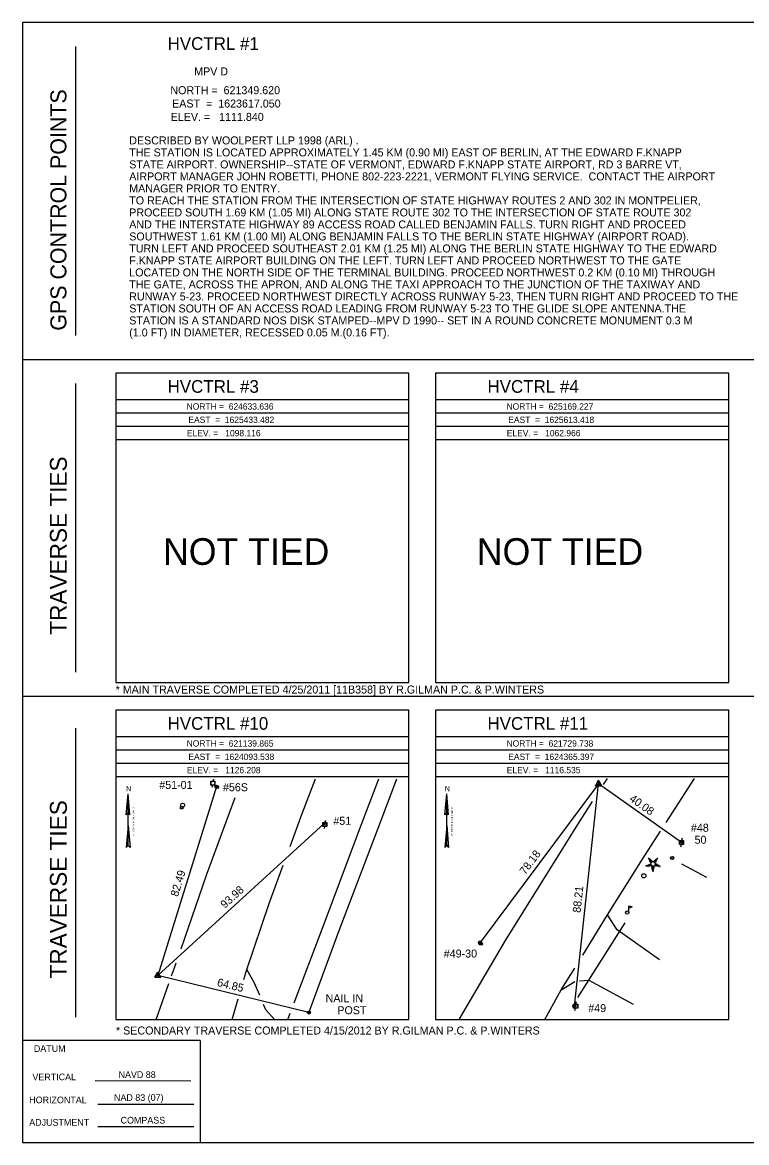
# Model space of a CAD drawing. Extents: x 1624370 to 1625010, y 624015 to 624435.
# Drawn here: x 1624369.8 to 1624641.5, y 624015.5 to 624435.5 of the extents above; entities that cross this region are included whole.
import ezdxf

# ---------------------------------------------------------------- set-up
doc = ezdxf.new("R2010")
doc.units = 0
for name, color, linetype in [('C_C', 7, 'Continuous'), ('CBP', 7, 'Continuous'), ('CPBM', 7, 'Continuous'), ('CPSM', 7, 'Continuous'), ('DCP', 7, 'Continuous'), ('Default', 7, 'Continuous'), ('LAHR', 7, 'Continuous'), ('LFNC', 7, 'Continuous'), ('LMB', 7, 'Continuous'), ('LTC', 7, 'Continuous'), ('MPIP', 7, 'Continuous'), ('NBL1', 7, 'Continuous'), ('NBL2', 7, 'Continuous'), ('NNA_P', 7, 'Continuous'), ('PET', 7, 'Continuous'), ('RDP', 7, 'Continuous'), ('U_C', 7, 'Continuous'), ('UP', 7, 'Continuous'), ('UPGW', 7, 'Continuous'), ('USMH', 7, 'Continuous')]:
    doc.layers.add(name, color=color, linetype=linetype)

msp = doc.modelspace()

# ---------------------------------------------------------------- linework, layer by layer
at = {"layer": 'CBP'}
for centre, radius in [((1624442.59, 624148.98), 0.562), ((1624442.59, 624148.98), 0.075), ((1624483.06, 624135.07), 0.562), ((1624483.06, 624135.07), 0.075), ((1624617.02, 624127.94), 0.594), ((1624617.02, 624127.94), 0.0792), ((1624541.46, 624090.47), 0.594), ((1624541.46, 624090.47), 0.0792), ((1624576.87, 624066.64), 0.594), ((1624576.87, 624066.64), 0.0792), ((1624477.25, 624064.25), 0.562), ((1624477.25, 624064.25), 0.075)]:
    msp.add_circle(centre, radius, dxfattribs=at)
at = {"layer": 'CPBM'}
for p, q in [((1624429.08, 624140.64), (1624429.08, 624141.54)), ((1624429.08, 624141.54), (1624429.98, 624141.54)), ((1624429.53, 624141.09), (1624429.53, 624141.09)), ((1624429.53, 624141.09), (1624429.53, 624141.09)), ((1624429.98, 624141.54), (1624429.98, 624140.64)), ((1624429.98, 624140.64), (1624429.08, 624140.64))]:
    msp.add_line(p, q, dxfattribs=at)
at = {"layer": 'CPSM'}
for p, q in [((1624584.76, 624149.26), (1624585.94, 624151.32)), ((1624584.76, 624149.26), (1624585.94, 624149.95)), ((1624587.13, 624149.26), (1624585.94, 624151.32)), ((1624585.94, 624149.95), (1624585.94, 624151.32)), ((1624585.94, 624149.95), (1624585.94, 624149.95)), ((1624585.94, 624149.95), (1624587.13, 624149.26)), ((1624584.76, 624149.26), (1624587.13, 624149.26)), ((1624419.42, 624077.44), (1624420.54, 624079.39)), ((1624419.42, 624077.44), (1624420.54, 624078.09)), ((1624421.67, 624077.44), (1624420.54, 624079.39)), ((1624420.54, 624078.09), (1624420.54, 624079.39)), ((1624420.54, 624078.09), (1624420.54, 624078.09)), ((1624420.54, 624078.09), (1624421.67, 624077.44)), ((1624419.42, 624077.44), (1624421.67, 624077.44))]:
    msp.add_line(p, q, dxfattribs=at)
at = {"layer": 'DCP'}
msp.add_lwpolyline([(1624578.15, 624069.82), (1624595.86, 624097.89)], dxfattribs=at)
at = {"layer": 'Default'}
for p, q in [((1624585.94, 624149.95), (1624541.46, 624090.47)), ((1624576.87, 624066.64), (1624585.94, 624149.95)), ((1624617.02, 624127.94), (1624585.94, 624149.95)), ((1624442.59, 624148.98), (1624420.54, 624078.09)), ((1624420.54, 624078.09), (1624483.06, 624135.07)), ((1624477.25, 624064.25), (1624420.54, 624078.09))]:
    msp.add_line(p, q, dxfattribs=at)
at = {"layer": 'LAHR'}
for points in [[(1624471.7, 624067.84), (1624482.36, 624095.81), (1624496.94, 624134.52), (1624503.46, 624151.8)], [(1624626.55, 624114.93), (1624617.14, 624119.83)], [(1624469.34, 624061.64), (1624470.23, 624063.98)]]:
    msp.add_lwpolyline(points, dxfattribs=at)
at = {"layer": 'LFNC'}
msp.add_lwpolyline([(1624477.2, 624064.07), (1624488.68, 624094.95), (1624504.26, 624136.01), (1624510.24, 624151.8)], dxfattribs=at)
at = {"layer": 'LMB'}
for p, q in [((1624597.3, 624104.22), (1624598.53, 624103.85)), ((1624597.31, 624101.75), (1624597.31, 624104.22)), ((1624597.31, 624103.36), (1624598.53, 624103.84)), ((1624596.68, 624101.74), (1624596.68, 624101.74))]:
    msp.add_line(p, q, dxfattribs=at)
msp.add_circle((1624596.68, 624101.74), 0.623, dxfattribs=at)
at = {"layer": 'LTC'}
for p, q in [((1624604.56, 624122.02), (1624604.9, 624122.26)), ((1624604.76, 624121.58), (1624605.26, 624121.94)), ((1624604.94, 624120.05), (1624605.26, 624119.08)), ((1624604.96, 624121.14), (1624605.63, 624121.62)), ((1624605.16, 624120.69), (1624605.99, 624121.3)), ((1624605.37, 624120.26), (1624606.33, 624120.96)), ((1624605.37, 624120.26), (1624605.74, 624119.13)), ((1624606.33, 624120.96), (1624607.28, 624120.27)), ((1624606.73, 624121.26), (1624607.5, 624120.7)), ((1624607.28, 624120.27), (1624606.91, 624119.13)), ((1624607.09, 624121.59), (1624607.73, 624121.12)), ((1624607.7, 624120.01), (1624607.38, 624119.02)), ((1624607.44, 624121.92), (1624607.96, 624121.54)), ((1624607.79, 624122.25), (1624608.19, 624121.96)), ((1624603.64, 624119.44), (1624603.79, 624118.99)), ((1624604.08, 624119.64), (1624604.28, 624119.02)), ((1624604.51, 624119.85), (1624604.77, 624119.05)), ((1624606.91, 624119.13), (1624605.74, 624119.13)), ((1624606.87, 624118.65), (1624605.79, 624118.65)), ((1624606.79, 624118.18), (1624605.86, 624118.18)), ((1624606.71, 624117.7), (1624605.92, 624117.7)), ((1624606.63, 624117.23), (1624605.99, 624117.23)), ((1624608.12, 624119.77), (1624607.85, 624118.93)), ((1624608.54, 624119.54), (1624608.32, 624118.84)), ((1624608.96, 624119.3), (1624608.79, 624118.75))]:
    msp.add_line(p, q, dxfattribs=at)
at = {"layer": 'MPIP'}
for radius in [0.594, 0.0792]:
    msp.add_circle((1624613.52, 624122.18), radius, dxfattribs=at)
at = {"layer": 'NBL1'}
msp.add_lwpolyline([(1624369.79, 624015.47), (1625009.79, 624015.47), (1625009.79, 624435.47), (1624369.79, 624435.47)], close=True, dxfattribs=at)
at = {"layer": 'NBL2'}
for p, q in [((1624389.79, 624318.14), (1624389.79, 624426.47)), ((1624369.79, 624309.14), (1625009.79, 624309.14)), ((1624389.79, 624191.81), (1624389.79, 624300.14)), ((1624514.79, 624293.97), (1624404.79, 624293.97)), ((1624634.79, 624293.97), (1624524.79, 624293.97)), ((1624514.79, 624288.97), (1624404.79, 624288.97)), ((1624634.79, 624288.97), (1624524.79, 624288.97)), ((1624514.79, 624283.97), (1624404.79, 624283.97)), ((1624634.79, 624283.97), (1624524.79, 624283.97)), ((1624514.79, 624278.97), (1624404.79, 624278.97)), ((1624634.79, 624278.97), (1624524.79, 624278.97)), ((1624369.79, 624182.81), (1625009.79, 624182.81)), ((1624389.79, 624062.47), (1624389.79, 624170.81)), ((1624514.79, 624167.64), (1624404.79, 624167.64)), ((1624634.79, 624167.64), (1624524.79, 624167.64)), ((1624514.79, 624162.64), (1624404.79, 624162.64)), ((1624634.79, 624162.64), (1624524.79, 624162.64)), ((1624514.79, 624157.64), (1624404.79, 624157.64)), ((1624634.79, 624157.64), (1624524.79, 624157.64)), ((1624514.79, 624152.64), (1624404.79, 624152.64)), ((1624634.79, 624152.64), (1624524.79, 624152.64)), ((1624436.45, 624053.73), (1624369.79, 624053.73)), ((1624436.45, 624053.73), (1624436.45, 624015.47)), ((1624436.45, 624053.73), (1624436.45, 624015.47)), ((1624397.03, 624038.7), (1624433.03, 624038.67)), ((1624398.14, 624029.93), (1624434.14, 624029.93)), ((1624398.14, 624021.49), (1624434.14, 624021.46))]:
    msp.add_line(p, q, dxfattribs=at)
for points in [[(1624404.79, 624187.97), (1624514.79, 624187.97), (1624514.79, 624303.97), (1624404.79, 624303.97)], [(1624524.79, 624187.97), (1624634.79, 624187.97), (1624634.79, 624303.97), (1624524.79, 624303.97)], [(1624404.79, 624061.64), (1624514.79, 624061.64), (1624514.79, 624177.64), (1624404.79, 624177.64)], [(1624524.79, 624061.64), (1624634.79, 624061.64), (1624634.79, 624177.64), (1624524.79, 624177.64)]]:
    msp.add_lwpolyline(points, close=True, dxfattribs=at)
at = {"layer": 'NNA_P'}
for p, q in [((1624408.76, 624138.4), (1624409.45, 624146.19)), ((1624409.46, 624126.81), (1624409.45, 624146.19)), ((1624410.15, 624138.4), (1624409.45, 624146.19)), ((1624528.28, 624138.4), (1624528.97, 624146.19)), ((1624528.97, 624126.81), (1624528.97, 624146.19)), ((1624529.66, 624138.4), (1624528.97, 624146.19)), ((1624408.76, 624138.4), (1624409.45, 624139.16)), ((1624410.15, 624138.4), (1624409.46, 624139.16)), ((1624528.28, 624138.4), (1624528.97, 624139.16)), ((1624529.67, 624138.4), (1624528.97, 624139.16)), ((1624409.46, 624134.34), (1624408.74, 624126.17)), ((1624409.45, 624134.34), (1624410.18, 624126.17)), ((1624528.97, 624134.34), (1624528.25, 624126.17)), ((1624528.97, 624134.34), (1624529.69, 624126.17)), ((1624409.46, 624126.81), (1624408.74, 624126.17)), ((1624409.46, 624126.81), (1624410.18, 624126.17)), ((1624528.97, 624126.81), (1624528.25, 624126.17)), ((1624528.97, 624126.81), (1624529.69, 624126.17))]:
    msp.add_line(p, q, dxfattribs=at)
at = {"layer": 'PET'}
for points in [[(1624470.25, 624126.53), (1624474.79, 624138.89), (1624479.8, 624151.8)], [(1624587.79, 624149.77), (1624589.24, 624152.03)], [(1624611.26, 624135.53), (1624621.9, 624152.03)], [(1624429.3, 624088.12), (1624438.99, 624116.1), (1624449.62, 624144.9)], [(1624533.6, 624061.64), (1624550.99, 624091.28), (1624578.17, 624134.77), (1624583.7, 624143.4)], [(1624579.99, 624085.73), (1624589.28, 624100.81), (1624602.4, 624121.8), (1624609.13, 624132.22)], [(1624452.86, 624076.66), (1624453.96, 624080.43), (1624462.4, 624105.18), (1624467.66, 624119.47)], [(1624425.76, 624077.98), (1624426.86, 624081.05), (1624427.51, 624082.92)], [(1624565.76, 624061.64), (1624571.96, 624072.7), (1624577, 624080.88)], [(1624419.92, 624061.64), (1624424.73, 624075.1)], [(1624448.47, 624061.64), (1624450.72, 624069.36)]]:
    msp.add_lwpolyline(points, dxfattribs=at)
at = {"layer": 'RDP'}
for points in [[(1624608.81, 624084.01), (1624592.91, 624095.28), (1624589.28, 624100.81)], [(1624458.83, 624070.7), (1624456.8, 624075.51), (1624453.96, 624080.43)], [(1624571.96, 624072.7), (1624577.05, 624075.93)], [(1624578.75, 624076.08), (1624582.23, 624076.39), (1624598.96, 624067.42)], [(1624464.34, 624061.64), (1624461.16, 624065.19), (1624460.29, 624067.23)]]:
    msp.add_lwpolyline(points, dxfattribs=at)
at = {"layer": 'UP'}
for p, q in [((1624440.51, 624149.47), (1624440.51, 624150.97)), ((1624440.51, 624150.97), (1624442.01, 624150.97)), ((1624442.01, 624149.47), (1624440.51, 624149.47)), ((1624441.04, 624148.72), (1624441.26, 624149.47)), ((1624441.49, 624151.72), (1624441.26, 624150.97)), ((1624441.26, 624150.22), (1624441.26, 624150.22)), ((1624442.01, 624150.97), (1624442.01, 624149.47)), ((1624482.56, 624134), (1624482.56, 624135.5)), ((1624482.56, 624135.5), (1624484.06, 624135.5)), ((1624484.06, 624134), (1624482.56, 624134)), ((1624483.08, 624133.25), (1624483.31, 624134)), ((1624483.53, 624136.25), (1624483.31, 624135.5)), ((1624483.31, 624134.75), (1624483.31, 624134.75)), ((1624484.06, 624135.5), (1624484.06, 624134)), ((1624616.28, 624127.2), (1624616.28, 624128.79)), ((1624616.28, 624128.79), (1624617.86, 624128.79)), ((1624617.3, 624129.58), (1624617.07, 624128.79)), ((1624617.86, 624128.79), (1624617.86, 624127.2)), ((1624617.86, 624127.2), (1624616.28, 624127.2)), ((1624616.83, 624126.41), (1624617.07, 624127.2)), ((1624617.07, 624128), (1624617.07, 624128)), ((1624576.51, 624065.82), (1624576.51, 624067.41)), ((1624576.51, 624067.41), (1624578.1, 624067.41)), ((1624578.1, 624065.82), (1624576.51, 624065.82)), ((1624577.07, 624065.03), (1624577.31, 624065.82)), ((1624577.54, 624068.2), (1624577.31, 624067.41)), ((1624577.31, 624066.62), (1624577.31, 624066.62)), ((1624578.1, 624067.41), (1624578.1, 624065.82))]:
    msp.add_line(p, q, dxfattribs=at)
for centre, radius in [((1624441.26, 624150.22), 0.75), ((1624483.31, 624134.75), 0.75), ((1624617.07, 624128), 0.792), ((1624577.31, 624066.62), 0.792)]:
    msp.add_circle(centre, radius, dxfattribs=at)
at = {"layer": 'UPGW'}
for centre, radius in [((1624442.85, 624148.78), 0.562), ((1624442.85, 624148.78), 0.075), ((1624541.77, 624090.05), 0.594), ((1624541.77, 624090.05), 0.0792)]:
    msp.add_circle(centre, radius, dxfattribs=at)
at = {"layer": 'USMH'}
for p, q in [((1624429.89, 624141.97), (1624429.89, 624141.97)), ((1624430.64, 624141.97), (1624430.64, 624141.97)), ((1624602.91, 624115.51), (1624602.91, 624115.51)), ((1624603.7, 624115.51), (1624603.7, 624115.51))]:
    msp.add_line(p, q, dxfattribs=at)
for centre, radius in [((1624429.89, 624141.97), 0.75), ((1624602.91, 624115.51), 0.792)]:
    msp.add_circle(centre, radius, dxfattribs=at)

# ---------------------------------------------------------------- texts
at = {"layer": 'C_C'}
for s, p in [('NAIL IN', (1624483.54, 624068.1)), ('POST', (1624487.94, 624063.6))]:
    msp.add_text(s, height=3, dxfattribs=at).set_placement(p)
at = {"layer": 'Default'}
for s, height, p in [('DESCRIBED BY WOOLPERT LLP 1998 (ARL) .  ', 3, (1624409.87, 624389.73)), ('THE STATION IS LOCATED APPROXIMATELY 1.45 KM (0.90 MI) EAST OF BERLIN, AT THE EDWARD F.KNAPP ', 3, (1624409.87, 624385.23)), ('STATE AIRPORT. OWNERSHIP--STATE OF VERMONT, EDWARD F.KNAPP STATE AIRPORT, RD 3 BARRE VT, ', 3, (1624409.87, 624380.73)), ('AIRPORT MANAGER JOHN ROBETTI, PHONE 802-223-2221, VERMONT FLYING SERVICE.  CONTACT THE AIRPORT ', 3, (1624409.87, 624376.23)), ('MANAGER PRIOR TO ENTRY.  ', 3, (1624409.87, 624371.73)), ('TO REACH THE STATION FROM THE INTERSECTION OF STATE HIGHWAY ROUTES 2 AND 302 IN MONTPELIER, ', 3, (1624409.87, 624367.23)), ('PROCEED SOUTH 1.69 KM (1.05 MI) ALONG STATE ROUTE 302 TO THE INTERSECTION OF STATE ROUTE 302 ', 3, (1624409.87, 624362.73)), ('AND THE INTERSTATE HIGHWAY 89 ACCESS ROAD CALLED BENJAMIN FALLS. TURN RIGHT AND PROCEED ', 3, (1624409.87, 624358.23)), ('SOUTHWEST 1.61 KM (1.00 MI) ALONG BENJAMIN FALLS TO THE BERLIN STATE HIGHWAY (AIRPORT ROAD). ', 3, (1624409.87, 624353.73)), ('TURN LEFT AND PROCEED SOUTHEAST 2.01 KM (1.25 MI) ALONG THE BERLIN STATE HIGHWAY TO THE EDWARD ', 3, (1624409.87, 624349.23)), ('F.KNAPP STATE AIRPORT BUILDING ON THE LEFT. TURN LEFT AND PROCEED NORTHWEST TO THE GATE ', 3, (1624409.87, 624344.73)), ('LOCATED ON THE NORTH SIDE OF THE TERMINAL BUILDING. PROCEED NORTHWEST 0.2 KM (0.10 MI) THROUGH ', 3, (1624409.87, 624340.23)), ('THE GATE, ACROSS THE APRON, AND ALONG THE TAXI APPROACH TO THE JUNCTION OF THE TAXIWAY AND ', 3, (1624409.87, 624335.73)), ('RUNWAY 5-23. PROCEED NORTHWEST DIRECTLY ACROSS RUNWAY 5-23, THEN TURN RIGHT AND PROCEED TO THE ', 3, (1624409.87, 624331.23)), ('STATION SOUTH OF AN ACCESS ROAD LEADING FROM RUNWAY 5-23 TO THE GLIDE SLOPE ANTENNA.THE ', 3, (1624409.87, 624326.73)), ('STATION IS A STANDARD NOS DISK STAMPED--MPV D 1990-- SET IN A ROUND CONCRETE MONUMENT 0.3 M ', 3, (1624409.87, 624322.23)), ('(1.0 FT) IN DIAMETER, RECESSED 0.05 M.(0.16 FT).', 3, (1624409.87, 624317.73)), ('NOT TIED', 10, (1624422.54, 624232.09)), ('NOT TIED', 10, (1624540.27, 624232.09)), ('* MAIN TRAVERSE COMPLETED 4/25/2011 [11B358] BY R.GILMAN P.C. & P.WINTERS ', 3, (1624404.77, 624183.84)), ('* SECONDARY TRAVERSE COMPLETED 4/15/2012 BY R.GILMAN P.C. & P.WINTERS ', 3, (1624404.91, 624056))]:
    msp.add_text(s, height=height, dxfattribs=at).set_placement(p)
for s, rotation, p in [('40.08', 324.6947, (1624597.23, 624143.8)), ('78.18', 53.21, (1624558.43, 624115.66)), ('82.49', 72.7256, (1624428.11, 624107.47)), ('93.98', 42.3472, (1624445.76, 624103.1)), ('88.21', 83.7816, (1624579.16, 624101.53)), ('64.85', 346.29, (1624442.64, 624074.24))]:
    msp.add_text(s, height=3, rotation=rotation, dxfattribs=at).set_placement(p)
at = {"layer": 'LTC'}
msp.add_text('.', height=0.986, rotation=270, dxfattribs=at).set_placement((1624606.22, 624120.02))
at = {"layer": 'NBL2'}
for s, height, p in [('     HVCTRL #1     ', 4.75, (1624415.43, 624425.17)), ('        MPV D       ', 3, (1624425.31, 624415.6)), ('NORTH =  621349.620 ', 3, (1624425.31, 624408.55)), ('EAST  =  1623617.050', 3, (1624425.97, 624403.55)), ('ELEV. =   1111.840  ', 3, (1624425.42, 624398.55)), ('     HVCTRL #3     ', 4.75, (1624415.43, 624296.6)), ('     HVCTRL #4     ', 4.75, (1624535.43, 624296.6)), ('NORTH =  624633.636 ', 2.375, (1624431.4, 624290.29)), ('NORTH =  625169.227 ', 2.375, (1624551.4, 624290.29)), ('EAST  =  1625433.482', 2.375, (1624432.06, 624285.29)), ('EAST  =  1625613.418', 2.375, (1624552.06, 624285.29)), ('ELEV. =   1098.116  ', 2.375, (1624431.51, 624280.29)), ('ELEV. =   1062.966  ', 2.375, (1624551.51, 624280.29)), ('     HVCTRL #10    ', 4.75, (1624415.43, 624170.27)), ('     HVCTRL #11    ', 4.75, (1624535.43, 624170.27)), ('NORTH =  621139.865 ', 2.375, (1624431.4, 624163.95)), ('NORTH =  621729.738 ', 2.375, (1624551.4, 624163.95)), ('EAST  =  1624093.538', 2.375, (1624432.05, 624158.95)), ('EAST  =  1624365.397', 2.375, (1624552.05, 624158.95)), ('ELEV. =   1126.208  ', 2.375, (1624431.51, 624153.95)), ('ELEV. =   1116.535  ', 2.375, (1624551.51, 624153.95)), ('DATUM', 2.5, (1624374.1, 624049.49)), ('  NAVD 88 ', 2.5, (1624404.01, 624039.71)), ('HORIZONTAL', 2.5, (1624372.36, 624030.23)), ('NAD 83 (07)', 2.5, (1624404.16, 624031.1)), ('ADJUSTMENT', 2.5, (1624372.36, 624021.79)), ('  COMPASS ', 2.5, (1624404.78, 624022.62))]:
    msp.add_text(s, height=height, dxfattribs=at).set_placement(p)
for s, height, rotation, p in [('GPS CONTROL POINTS', 6, 90, (1624386.29, 624319.89)), ('TRAVERSE TIES', 6.3332, 90, (1624386.45, 624205.91)), ('TRAVERSE TIES', 6.3332, 90, (1624386.45, 624077.02)), ('VERTICAL', 2.5, 0.1439, (1624373.56, 624038.82))]:
    msp.add_text(s, height=height, rotation=rotation, dxfattribs=at).set_placement(p)
at = {"layer": 'NNA_P'}
for p in [(1624408.69, 624147.2), (1624528.21, 624147.2)]:
    msp.add_text('N', height=1.97, dxfattribs=at).set_placement(p)
for p in [(1624411.81, 624130.38), (1624531.32, 624130.38)]:
    msp.add_text('VT STATE PLANE GRID', height=0.7, rotation=90.0204, dxfattribs=at).set_placement(p)
at = {"layer": 'U_C'}
for s, p in [('#51-01', (1624421.13, 624148.08)), ('#56S', (1624445.03, 624147.21)), ('#51', (1624486.45, 624134.62)), ('#48', (1624620.59, 624132.02)), ('50', (1624621.95, 624127.52)), ('#49-30', (1624527.87, 624084.86)), ('#49', (1624582.07, 624064.4))]:
    msp.add_text(s, height=3, dxfattribs=at).set_placement(p)

doc.saveas('drawing.dxf')
